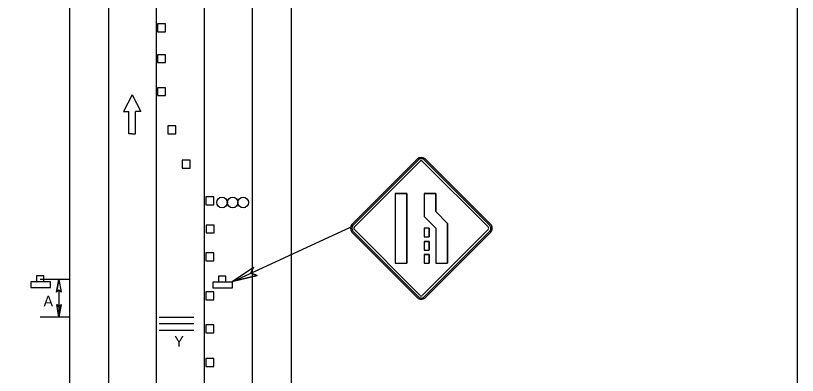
# Model space of a CAD drawing. Extents: x 0 to 1549163, y -476626 to 622136.
# Drawn here: x 15.545 to 19.938, y 12.007 to 14.026 of the extents above; entities that cross this region are included whole.
import ezdxf

# ---------------------------------------------------------------- set-up
doc = ezdxf.new("R2010")
doc.units = 0
for name, color, linetype in [('DETL-DIMS', 7, 'Continuous'), ('DETL-LINE', 7, 'Continuous'), ('DETL-NOTE', 7, 'Continuous'), ('USER-BORD', 7, 'Continuous'), ('USER-CLIP', 7, 'Continuous')]:
    doc.layers.add(name, color=color, linetype=linetype)

# ---------------------------------------------------------------- blocks, each defined once
blk = doc.blocks.new('PANEL0')
at = {"layer": 'USER-BORD'}
for centre in [(0.00309, -0.00012), (0.00928, -0.00012), (0.01546, -0.00012)]:
    blk.add_circle(centre, 0.00312, dxfattribs=at)
blk = doc.blocks.new('DIR4')
at = {"layer": 'USER-BORD'}
for p, q in [((0, 0.0001), (-0.0034, -0.0048)), ((0, 0.0001), (0.0034, -0.0048)), ((-0.0034, -0.0048), (-0.0013, -0.0048)), ((-0.0013, -0.0113), (-0.0013, -0.0048)), ((0.0034, -0.0048), (0.0013, -0.0048)), ((0.0013, -0.0113), (0.0013, -0.0048)), ((-0.0001, -0.0113), (-0.0013, -0.0113)), ((-0.0001, -0.0113), (0.0001, -0.0113)), ((0.0001, -0.0113), (0.0013, -0.0113))]:
    blk.add_line(p, q, dxfattribs=at)
blk = doc.blocks.new('SIGN15')
at = {"layer": 'USER-BORD'}
for points in [[(-0.0013, 0.0018), (0.0011, 0.0019), (0.0011, 0.0037), (-0.0013, 0.0037)], [(-0.0031, 0.0018), (-0.0031, 0), (0.0032, 0), (0.0032, 0.0018)]]:
    blk.add_lwpolyline(points, close=True, dxfattribs=at)

msp = doc.modelspace()

# ---------------------------------------------------------------- linework, layer by layer
at = {"layer": 'DETL-DIMS'}
for p, q in [((16.7613, 12.5322), (17.4266, 12.8383)), ((16.7611, 12.5334), (16.8814, 12.6145)), ((16.867, 12.5805), (16.8814, 12.6145)), ((16.7611, 12.5334), (16.902, 12.5683)), ((16.902, 12.5683), (16.867, 12.5805)), ((15.7876, 12.5461), (15.775, 12.4746)), ((15.7876, 12.5461), (15.8002, 12.4746)), ((15.775, 12.4746), (15.7876, 12.4881)), ((15.7876, 12.4881), (15.7875, 12.3538)), ((15.7876, 12.4881), (15.8002, 12.4746)), ((15.7886, 12.3332), (15.776, 12.4047)), ((15.7886, 12.3912), (15.776, 12.4047)), ((15.7886, 12.3332), (15.8012, 12.4047)), ((15.8012, 12.4047), (15.7886, 12.3912))]:
    msp.add_line(p, q, dxfattribs=at)
for points in [[(16.902, 12.5683), (16.7611, 12.5334), (16.8814, 12.6145), (16.867, 12.5805)], [(15.775, 12.4746), (15.7876, 12.5461), (15.8002, 12.4746), (15.7876, 12.4881)], [(15.8012, 12.4047), (15.7886, 12.3332), (15.776, 12.4047), (15.7886, 12.3912)]]:
    msp.add_lwpolyline(points, close=True, dxfattribs=at)
at = {"layer": 'DETL-LINE'}
for p, q in [((16.3341, 16.3778), (16.3341, 8.4351)), ((15.8482, 15.9277), (15.8482, 7.985)), ((16.0672, 15.9278), (16.0672, 7.9851)), ((16.0673, 15.9277), (16.0673, 7.985)), ((16.3341, 15.9278), (16.3341, 7.9851)), ((16.6039, 15.9278), (16.6039, 7.9851)), ((16.6039, 15.9278), (16.6039, 7.9851)), ((16.8736, 15.9278), (16.8736, 7.9851)), ((17.0935, 15.9278), (17.0935, 7.9851)), ((16.6039, 15.8673), (16.6039, 7.9246)), ((17.4349, 12.8541), (17.803, 13.2222)), ((17.8456, 13.2222), (18.2145, 12.8541)), ((17.4403, 12.8487), (17.8084, 13.2168)), ((17.4488, 12.8401), (17.8169, 13.2083)), ((17.8317, 13.2083), (18.2006, 12.8401)), ((17.8402, 13.2168), (18.2091, 12.8487)), ((17.6778, 13.0281), (17.6778, 12.6374)), ((17.6778, 13.0281), (17.7434, 13.0281)), ((17.7434, 13.0281), (17.6778, 13.0281)), ((17.6778, 13.0281), (17.6778, 12.6374)), ((17.7434, 13.0281), (17.7434, 12.6374)), ((17.7434, 12.6374), (17.7434, 13.0281)), ((17.8404, 13.0281), (17.8404, 12.8992)), ((17.8404, 13.0281), (17.906, 13.0281)), ((17.906, 13.0281), (17.8404, 13.0281)), ((17.8404, 13.0281), (17.8404, 12.8992)), ((17.906, 13.0281), (17.906, 12.9264)), ((17.906, 12.9264), (17.906, 13.0281)), ((17.9724, 12.86), (17.906, 12.9264)), ((17.9724, 12.86), (17.906, 12.9264)), ((17.9068, 12.8328), (17.8404, 12.8992)), ((17.8404, 12.8992), (17.9068, 12.8328)), ((17.8404, 12.8328), (17.8404, 12.7839)), ((17.8694, 12.8328), (17.8404, 12.8328)), ((17.8404, 12.8328), (17.8404, 12.7839)), ((17.8694, 12.8328), (17.8694, 12.7839)), ((17.8694, 12.7839), (17.8694, 12.8328)), ((17.9068, 12.8328), (17.9068, 12.6374)), ((17.9068, 12.8328), (17.9068, 12.6374)), ((17.9724, 12.86), (17.9724, 12.6374)), ((17.9724, 12.6374), (17.9724, 12.86)), ((17.803, 12.4426), (17.4349, 12.8115)), ((17.8084, 12.448), (17.4403, 12.8169)), ((17.8169, 12.4565), (17.4488, 12.8254)), ((18.2006, 12.8254), (17.8317, 12.4565)), ((18.2091, 12.8169), (17.8402, 12.448)), ((17.8404, 12.7839), (17.8694, 12.7839)), ((17.8404, 12.7839), (17.8694, 12.7839)), ((18.2145, 12.8115), (17.8456, 12.4426)), ((17.8404, 12.7595), (17.8694, 12.7595)), ((17.8404, 12.7595), (17.8404, 12.7107)), ((17.8694, 12.7595), (17.8404, 12.7595)), ((17.8404, 12.7595), (17.8404, 12.7107)), ((17.8694, 12.7595), (17.8694, 12.7107)), ((17.8694, 12.7107), (17.8694, 12.7595)), ((17.8404, 12.7107), (17.8694, 12.7107)), ((17.8404, 12.7107), (17.8694, 12.7107)), ((17.8404, 12.6863), (17.8694, 12.6863)), ((17.8404, 12.6863), (17.8404, 12.6374)), ((17.8694, 12.6863), (17.8404, 12.6863)), ((17.8404, 12.6863), (17.8404, 12.6374)), ((17.8694, 12.6863), (17.8694, 12.6374)), ((17.8694, 12.6374), (17.8694, 12.6863)), ((17.6778, 12.6374), (17.7434, 12.6374)), ((17.6778, 12.6374), (17.7434, 12.6374)), ((17.8404, 12.6374), (17.8694, 12.6374)), ((17.8404, 12.6374), (17.8694, 12.6374)), ((17.9068, 12.6374), (17.9724, 12.6374)), ((17.9068, 12.6374), (17.9724, 12.6374)), ((15.8482, 12.5452), (15.6835, 12.5452)), ((15.8482, 12.3332), (15.6828, 12.3332)), ((16.3511, 12.3333), (16.5472, 12.3333)), ((16.3511, 12.298), (16.5472, 12.298)), ((16.3511, 12.2601), (16.5472, 12.2601))]:
    msp.add_line(p, q, dxfattribs=at)
for points in [[(16.3431, 13.9362), (16.3879, 13.9362), (16.3879, 13.981), (16.3431, 13.981)], [(16.3431, 13.7624), (16.3879, 13.7624), (16.3879, 13.8072), (16.3431, 13.8072)], [(16.3431, 13.5772), (16.3879, 13.5772), (16.3879, 13.622), (16.3431, 13.622)], [(16.4007, 13.3631), (16.4455, 13.3631), (16.4455, 13.4079), (16.4007, 13.4079)], [(16.4813, 13.1711), (16.5261, 13.1711), (16.5261, 13.2159), (16.4813, 13.2159)], [(16.6133, 12.9637), (16.6581, 12.9637), (16.6581, 13.0085), (16.6133, 13.0085)], [(16.6161, 12.8063), (16.6609, 12.8063), (16.6609, 12.8511), (16.6161, 12.8511)], [(16.6133, 12.6508), (16.6581, 12.6508), (16.6581, 12.6956), (16.6133, 12.6956)], [(16.6133, 12.4309), (16.6581, 12.4309), (16.6581, 12.4757), (16.6133, 12.4757)], [(16.6133, 12.2456), (16.6581, 12.2456), (16.6581, 12.2904), (16.6133, 12.2904)], [(16.6133, 12.0575), (16.6581, 12.0575), (16.6581, 12.1023), (16.6133, 12.1023)]]:
    msp.add_lwpolyline(points, close=True, dxfattribs=at)
for points in [[(16.3342, 13.734), (16.3342, 13.6777)], [(16.604, 13.734), (16.604, 13.6777)], [(16.3342, 13.6777), (16.3342, 13.6215)], [(16.604, 13.6777), (16.604, 13.6215)], [(16.3342, 13.284), (16.3342, 13.2277)], [(16.604, 13.284), (16.604, 13.2277)], [(16.3342, 13.2277), (16.3342, 13.1715)], [(16.604, 13.2277), (16.604, 13.1715)], [(16.3342, 12.834), (16.3342, 12.7777)], [(16.604, 12.834), (16.604, 12.7777)], [(16.3342, 12.7777), (16.3342, 12.7215)], [(16.604, 12.7777), (16.604, 12.7215)], [(16.3342, 12.384), (16.3342, 12.3277)], [(16.604, 12.384), (16.604, 12.3277)], [(16.3342, 12.3277), (16.3342, 12.2715)], [(16.604, 12.3277), (16.604, 12.2715)]]:
    msp.add_lwpolyline(points, dxfattribs=at)
for centre, radius, start, end in [((17.8243, 13.2007), 0.0303, 45.06, 135), ((17.8243, 13.2012), 0.0223, 45.06, 135), ((17.8243, 13.2013), 0.0101, 45.06, 135), ((17.4564, 12.8328), 0.0303, 135, 224.9399), ((17.4559, 12.8328), 0.0223, 135, 224.9399), ((17.4557, 12.8328), 0.0101, 135, 224.9399), ((18.1936, 12.8328), 0.0101, 315, 45.0601), ((18.1935, 12.8328), 0.0223, 315, 45.0601), ((18.193, 12.8328), 0.0303, 315, 45.0601), ((17.8243, 12.4641), 0.0303, 224.94, 315), ((17.8243, 12.4636), 0.0223, 224.94, 315), ((17.8243, 12.4634), 0.0101, 224.94, 315)]:
    msp.add_arc(centre, radius, start, end, dxfattribs=at)
at = {"layer": 'USER-CLIP'}
msp.add_lwpolyline([(19.9377, 16.6675), (11.4377, 16.6675), (11.4377, 5.6675), (19.9377, 5.6675)], close=True, dxfattribs=at)

# ---------------------------------------------------------------- block references
at = {"layer": 'DETL-LINE'}
for name, p, xscale, yscale in [('DIR4', (16.1997, 13.5808), 14.399999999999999, 19.2), ('PANEL0', (16.6753, 12.9789), 9.6, 9.6), ('SIGN15', (15.6845, 12.5012), 17.523809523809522, 17.523809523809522), ('SIGN15', (16.7071, 12.4991), 17.523809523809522, 17.523809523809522)]:
    msp.add_blockref(name, p, dxfattribs=dict(at, xscale=xscale, yscale=yscale))

# ---------------------------------------------------------------- texts
at = {"layer": 'DETL-NOTE'}
for s, p in [('A', (15.7019, 12.3939)), ('Y', (16.4368, 12.1677))]:
    msp.add_text(s, height=0.06, dxfattribs=at).set_placement(p)

doc.saveas('drawing.dxf')
